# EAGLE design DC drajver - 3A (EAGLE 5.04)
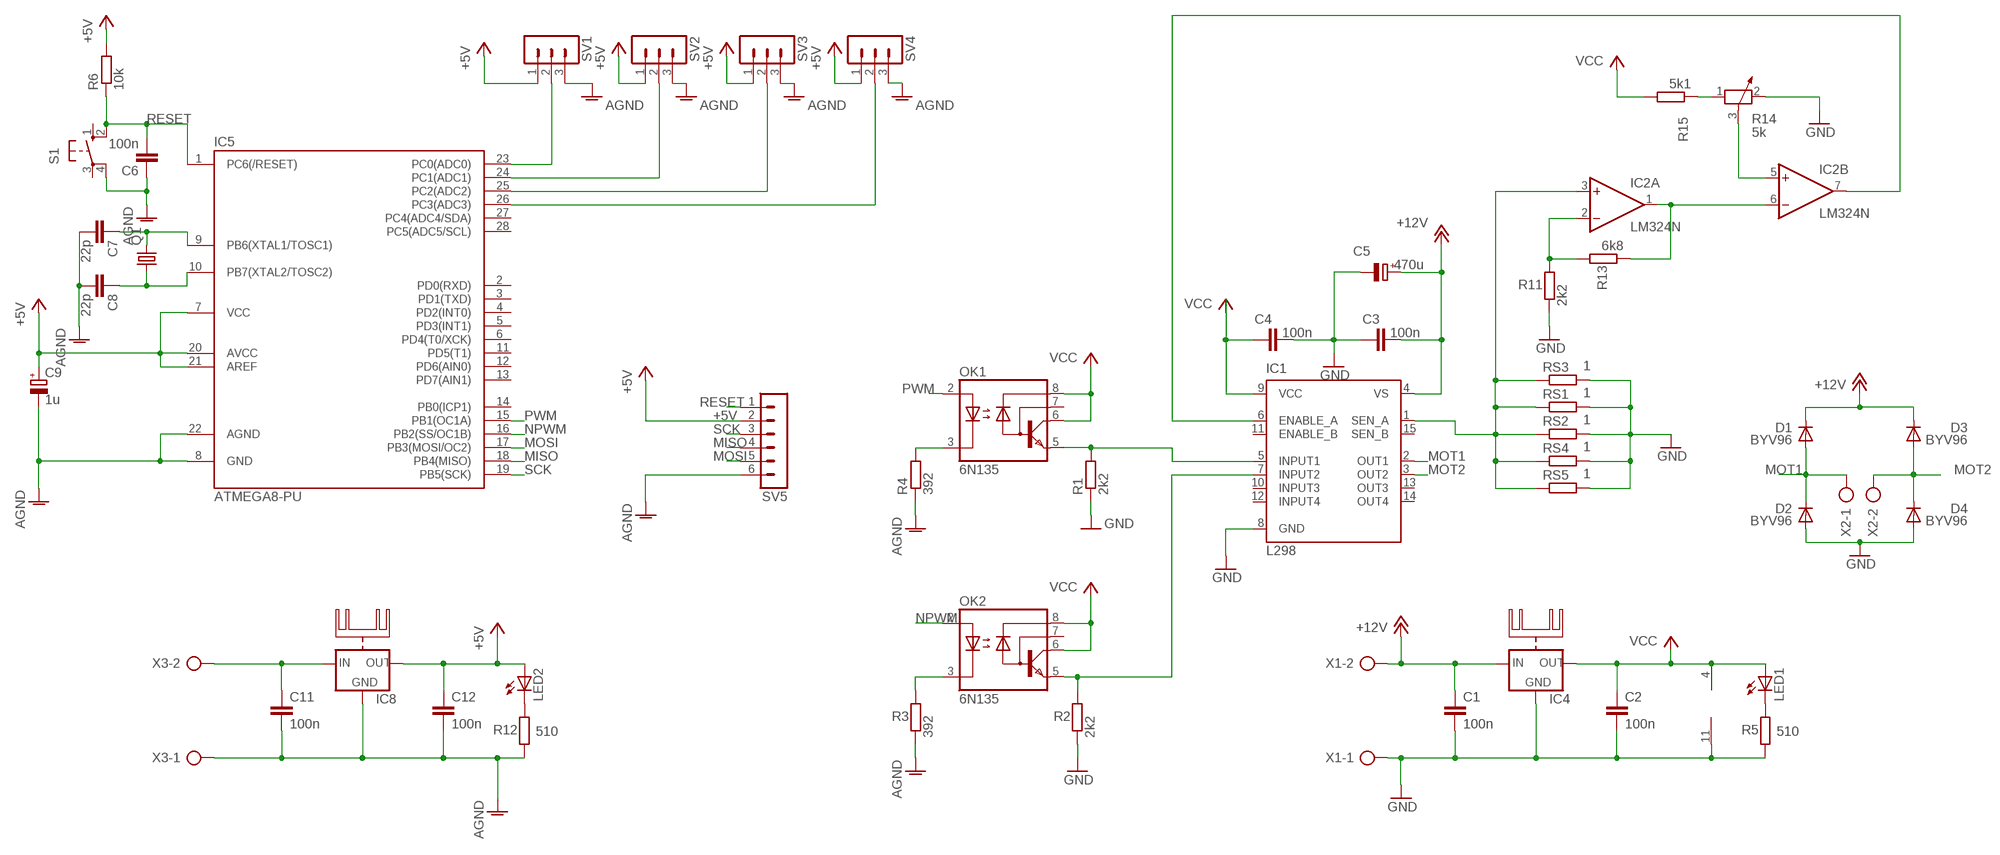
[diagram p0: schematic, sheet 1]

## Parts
C1  100n  C-EU050-024X044  [C050-024X044]
C2  100n  C-EU050-024X044  [C050-024X044]
C3  100n  C-EU050-024X044  [C050-024X044]
C4  100n  C-EU050-024X044  [C050-024X044]
C5  470u  CPOL-EUE3.5-8  [E3,5-8]
C6  100n  C-EU050-024X044  [C050-024X044]
C7  22p  C-EU050-024X044  [C050-024X044]
C8  22p  C-EU050-024X044  [C050-024X044]
C9  1u  CPOL-EUE2-4  [E2-4]
C11  100n  C-EU050-024X044  [C050-024X044]
C12  100n  C-EU050-024X044  [C050-024X044]
D1  BYV96  [SOD57-10]
D2  BYV96  [SOD57-10]
D3  BYV96  [SOD57-10]
D4  BYV96  [SOD57-10]
IC1  L298  [MULTIWATT-15]
IC2  LM324N  [DIL14]
IC4  78XXH  [78XXH]
IC5  ATMEGA8-PU  [DIL28-3]
IC8  78XXH  [78XXH]
LED1  LED3MM  [LED3MM]
LED2  LED3MM  [LED3MM]
OK1  6N135  [DIL08]
OK2  6N135  [DIL08]
Q1  CRYSTALHC49S  [HC49/S]
R1  2k2  R-EU_0207/7  [0207/7]
R2  2k2  R-EU_0207/7  [0207/7]
R3  392  R-EU_0207/7  [0207/7]
R4  392  R-EU_0207/7  [0207/7]
R5  510  R-EU_0207/7  [0207/7]
R6  10k  R-EU_0207/7  [0207/7]
R11  2k2  R-EU_0207/7  [0207/7]
R12  510  R-EU_0207/7  [0207/7]
R13  6k8  R-EU_0207/7  [0207/7]
R14  5k  POTENTIOMETER_PT-10  [PT-10]
R15  5k1  R-EU_0207/7  [0207/7]
RS1  1  R-EU_0617/5V  [0617V]
RS2  1  R-EU_0617/5V  [0617V]
RS3  1  R-EU_0617/5V  [0617V]
RS4  1  R-EU_0617/5V  [0617V]
RS5  1  R-EU_0617/5V  [0617V]
S1  10-XX  [B3F-10XX]
SV1  MA03-1  [MA03-1]
SV2  MA03-1  [MA03-1]
SV3  MA03-1  [MA03-1]
SV4  MA03-1  [MA03-1]
SV5  MA06-1  [MA06-1]
X1  AK500/2  [AK500/2]
X2  AK500/2  [AK500/2]
X3  AK500/2  [AK500/2]

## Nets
+5V: C9.+ C12.1 IC5.7(VCC) IC5.20(AVCC) IC5.21(AREF) IC8.OUT LED2.A R6.2 SV1.1 SV2.1 SV3.1 SV4.1 SV5.2
+12V: C1.1 C3.2 C5.+ D1.C D3.C IC1.4(VS) IC4.IN X1.2
AGND: C6.1 C7.2 C8.2 C9.- C11.2 C12.2 IC5.8(GND) IC5.22(AGND) IC8.GND R3.1 R4.1 R12.1 S1.4(P1) SV1.3 SV2.3 SV3.3 SV4.3 SV5.6 X3.1
GND: C1.2 C2.2 C3.1 C4.2 C5.- D2.A D4.A IC1.8(GND) IC2.11(P:V-) IC4.GND R1.1 R2.1 R5.1 R11.1 R14.2 RS1.2 RS2.2 RS3.2 RS4.2 RS5.2 X1.1
MISO: IC5.18(PB4(MISO)) SV5.4
MOSI: IC5.17(PB3(MOSI/OC2)) SV5.5
MOT1: D1.A D2.C IC1.2(OUT1) X2.1
MOT2: D3.A D4.C IC1.3(OUT2) X2.2
N$1: IC2.2(A:-IN) R11.2 R13.2
N$2: IC2.1(A:OUT) IC2.6(B:-IN) R13.1
N$3: LED1.K(C) R5.2
N$4: R14.1 R15.1
N$5: IC5.23(PC0(ADC0)) SV1.2
N$6: IC1.7(INPUT2) OK2.5(GND) R2.2
N$7: OK2.3(C) R3.2
N$8: OK1.3(C) R4.2
N$9: IC1.5(INPUT1) OK1.5(GND) R1.2
N$10: IC2.5(B:+IN) R14.3
N$12: IC5.24(PC1(ADC1)) SV2.2
N$13: C7.1 IC5.9(PB6(XTAL1/TOSC1)) Q1.2
N$14: C8.1 IC5.10(PB7(XTAL2/TOSC2)) Q1.1
N$15: IC1.1(SEN_A) IC2.3(A:+IN) RS1.1 RS2.1 RS3.1 RS4.1 RS5.1
N$16: IC5.25(PC2(ADC2)) SV3.2
N$17: IC5.26(PC3(ADC3)) SV4.2
N$22: C11.1 IC8.IN X3.2
N$23: LED2.K(C) R12.2
N$26: IC1.6(ENABLE_A) IC2.7(B:OUT)
NPWM: IC5.16(PB2(SS/OC1B)) OK2.2(A)
PWM: IC5.15(PB1(OC1A)) OK1.2(A)
RESET: C6.2 IC5.1(PC6(/RESET)) R6.1 S1.2(S1) SV5.1
SCK: IC5.19(PB5(SCK)) SV5.3
VCC: C2.1 C4.1 IC1.9(VCC) IC2.4(P:V+) IC4.OUT LED1.A OK1.6(VO) OK1.8(VCC) OK2.6(VO) OK2.8(VCC) R15.2
Unconnected: IC1.10(INPUT3) IC1.11(ENABLE_B) IC1.12(INPUT4) IC1.13(OUT3) IC1.14(OUT4) IC1.15(SEN_B) IC2.8(C:OUT) IC2.9(C:-IN) IC2.10(C:+IN) IC2.12(D:+IN) IC2.13(D:-IN) IC2.14(D:OUT) IC5.2(PD0(RXD)) IC5.3(PD1(TXD)) IC5.4(PD2(INT0)) IC5.5(PD3(INT1)) IC5.6(PD4(T0/XCK)) IC5.11(PD5(T1)) IC5.12(PD6(AIN0)) IC5.13(PD7(AIN1)) IC5.14(PB0(ICP1)) IC5.27(PC4(ADC4/SDA)) IC5.28(PC5(ADC5/SCL)) OK1.7(VB) OK2.7(VB) S1.1(S) S1.3(P)

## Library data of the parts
C1-C4 C6-C8 C11 C12 = rcl:C-EU: CAPACITOR, European symbol
C5 C9 = rcl:CPOL-EU: POLARIZED CAPACITOR, European symbol
D1-D4 = diode:BYV96: DIODE
IC1 = st-microelectronics:L298: DUAL FULL-BRIDGE DRIVER
IC2 = linear:LM324: OP AMP
IC4 IC8 = 78xx_with_heatsink:78XXH: VOLTAGE REGULATOR
IC5 = atmega8:ATMEGA8-PU
LED1 LED2 = led:LED: LED
OK1 OK2 = optocoupler:6N135: MOTOROLA OPTO COUPLER
Q1 = crystal:CRYSTAL: CRYSTAL
R1-R6 R11-R13 R15 RS1-RS5 = rcl:R-EU_: RESISTOR, European symbol
R14 = rcl:POTENTIOMETER_: Potentiometer
S1 = switch-omron:10-XX: OMRON SWITCH
SV1-SV4 = con-lstb:MA03-1: PIN HEADER
SV5 = con-lstb:MA06-1: PIN HEADER
X1-X3 = con-ptr500:AK500/2: CONNECTOR

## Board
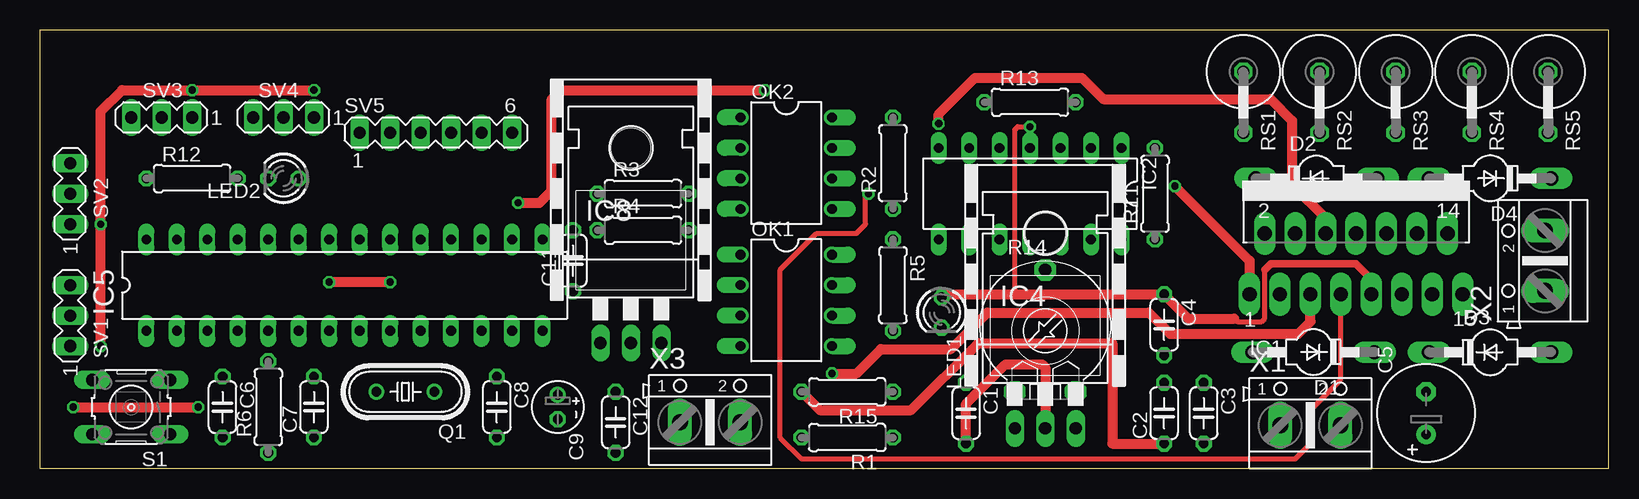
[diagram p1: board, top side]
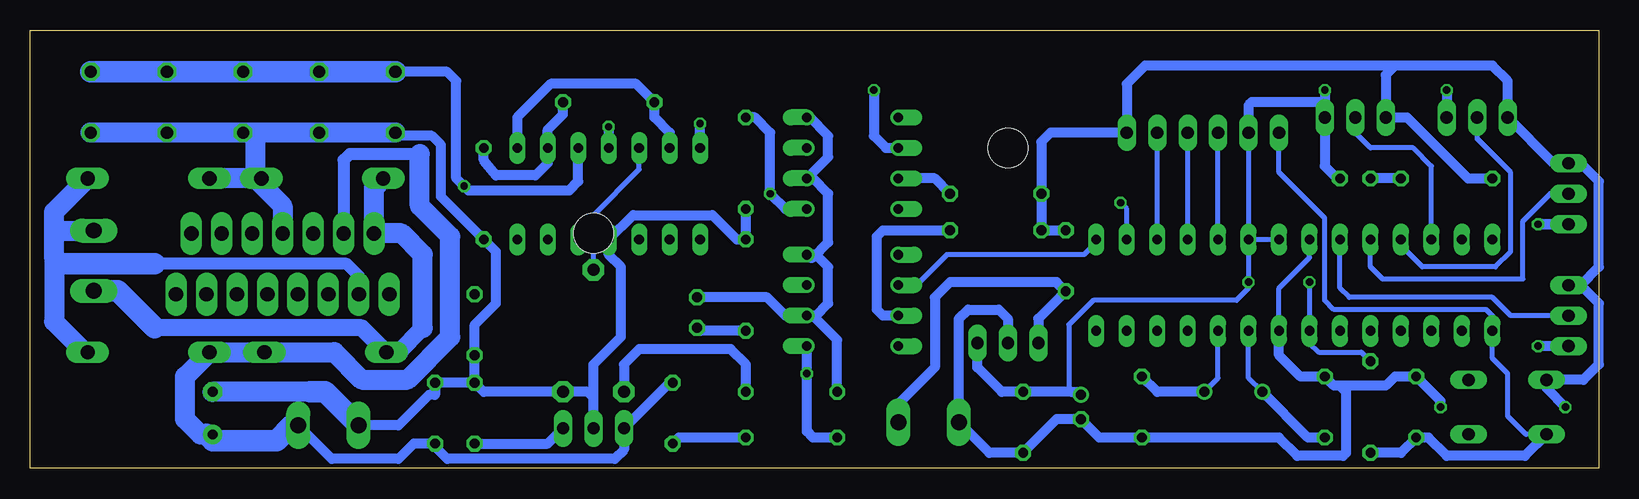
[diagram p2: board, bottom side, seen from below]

Size 130.79 x 36.5 mm. Coordinates in mm from the lower left corner, seen from the top.
Outline: 0,0 130.79,0 130.79,36.5 0,36.5 0,0
Copper layers (1*16): Top 0.035mm / dielectric 1.5mm / Bottom 0.035mm
Design rules "default": minimum track width 10mil, minimum drill 24mil, track to track 8mil, track to pad 8mil, pad to pad 8mil, via to via 8mil, smd to smd 8mil, copper to edge 40mil, drill to drill 8mil, minimum pad ring 10mil, minimum via ring 8mil, stop-mask expansion 4mil, vias tented up to drill 0mil, thermal gap 10mil

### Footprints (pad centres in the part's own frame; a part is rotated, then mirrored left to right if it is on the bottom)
C050-024X044 = drill 0.813 octagon: 1 -2.54,0; 2 2.54,0
E3,5-8 = drill 0.813 pad 1.6 round: + -1.778,0 | drill 0.813 pad 1.6 octagon: - 1.778,0
E2-4 = drill 0.813 pad 1.27 round: + -1.016,0 | drill 0.813 pad 1.27 octagon: - 1.016,0
SOD57-10 = drill 1.194 long: A 5.08,0; C -5.08,0
MULTIWATT-15 = drill 1.2 long: 1 -8.89,-7.62; 2 -7.62,-2.54; 3 -6.35,-7.62; 4 -5.08,-2.54; 5 -3.81,-7.62; 6 -2.54,-2.54; 7 -1.27,-7.62; 8 0,-2.54; 9 1.27,-7.62; 10 2.54,-2.54; 11 3.81,-7.62; 12 5.08,-2.54; 13 6.35,-7.62; 14 7.62,-2.54; 15 8.89,-7.62
DIL14 = drill 0.813 long: 1 -7.62,-3.81; 2 -5.08,-3.81; 3 -2.54,-3.81; 4 0,-3.81; 5 2.54,-3.81; 6 5.08,-3.81; 7 7.62,-3.81; 8 7.62,3.81; 9 5.08,3.81; 10 2.54,3.81; 11 0,3.81; 12 -2.54,3.81; 13 -5.08,3.81; 14 -7.62,3.81
78XXH = drill 1.016 long: GND 0,-5.08; IN -2.54,-5.08; OUT 2.54,-5.08 | hole 3.302: 0,11.176
DIL28-3 = drill 0.813 long: 1 -16.51,-3.81; 2 -13.97,-3.81; 3 -11.43,-3.81; 4 -8.89,-3.81; 5 -6.35,-3.81; 6 -3.81,-3.81; 7 -1.27,-3.81; 8 1.27,-3.81; 9 3.81,-3.81; 10 6.35,-3.81; 11 8.89,-3.81; 12 11.43,-3.81; 13 13.97,-3.81; 14 16.51,-3.81; 15 16.51,3.81; 16 13.97,3.81; 17 11.43,3.81; 18 8.89,3.81; 19 6.35,3.81; 20 3.81,3.81; 21 1.27,3.81; 22 -1.27,3.81; 23 -3.81,3.81; 24 -6.35,3.81; 25 -8.89,3.81; 26 -11.43,3.81; 27 -13.97,3.81; 28 -16.51,3.81
LED3MM = drill 0.813 octagon: A -1.27,0; K 1.27,0
DIL08 = drill 0.813 offset: 1 -3.81,-3.81; 2 -1.27,-3.81; 3 1.27,-3.81; 4 3.81,-3.81; 5 3.81,3.81; 6 1.27,3.81; 7 -1.27,3.81; 8 -3.81,3.81
HC49/S = drill 0.813 round: 1 -2.413,0; 2 2.413,0
0207/7 = drill 0.813 octagon: 1 -3.81,0; 2 3.81,0
PT-10 = drill 1.016 pad 1.778 octagon: 1 -2.54,-5.08; 2 2.54,-5.08; 3 0,5.08
0617V = drill 1.016 octagon: 1 -2.54,0; 2 2.54,0
B3F-10XX = drill 1.016 long: 1 -3.251,2.261; 2 3.251,2.261; 3 -3.251,-2.261; 4 3.251,-2.261
MA03-1 = drill 1.016 long: 1 -2.54,0; 2 0,0; 3 2.54,0
MA06-1 = drill 1.016 long: 1 -6.35,0; 2 -3.81,0; 3 -1.27,0; 4 1.27,0; 5 3.81,0; 6 6.35,0
AK500/2 = drill 1.321 long: 1 -2.515,0; 2 2.515,0

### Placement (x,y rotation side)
C1  77.22,4.57 270 top
C2  93.73,4.57 90 top
C3  97.03,4.57 270 top
C4  93.73,11.94 270 top
C5  115.57,4.57 90 top
C6  15.24,5.08 270 top
C7  22.86,5.08 90 top
C8  38.1,5.08 270 top
C9  43.18,5.08 270 top
C11  44.45,17.27 90 top
C12  48.01,3.81 270 top
D1  106.17,9.65 180 top
D2  106.43,24.13 0 top
D3  120.9,9.65 0 top
D4  120.9,24.13 180 top
IC1  109.73,22.1 0 top
IC2  82.55,22.86 180 top
IC4  83.82,8.38 0 top
IC5  25.4,15.24 0 top
IC8  49.28,15.49 0 top
LED1  75.18,12.95 270 top
LED2  20.32,24.13 180 top
OK1  62.23,13.97 270 top
OK2  62.23,25.4 270 top
Q1  30.48,6.35 180 top
R1  67.31,2.54 180 top
R2  71.12,25.4 90 top
R3  50.29,22.86 0 top
R4  50.29,19.81 0 top
R5  71.12,15.24 270 top
R6  19.05,5.08 90 top
R11  92.96,22.86 90 top
R12  12.7,24.13 0 top
R13  82.55,30.48 0 top
R14  83.82,11.43 0 top
R15  67.31,6.35 180 top
RS1  100.33,30.48 270 top
RS2  106.68,30.48 270 top
RS3  113.03,30.48 270 top
RS4  119.38,30.48 270 top
RS5  125.73,30.48 270 top
S1  7.62,5.08 180 top
SV1  2.54,12.7 90 top
SV2  2.54,22.86 90 top
SV3  10.16,29.21 180 top
SV4  20.32,29.21 180 top
SV5  33.02,27.94 0 top
X1  105.92,3.56 0 top
X2  125.48,17.27 90 top
X3  55.88,3.81 0 top

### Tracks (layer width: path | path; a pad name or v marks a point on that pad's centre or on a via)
+5V  (via drill 0.6)
  Top 0.813: v5.08,10.16 5.08,20.07 | 5.08,20.07 v5.08,20.32 | 5.08,20.07 5.08,29.72 6.86,31.5 v12.7,31.5 v22.86,31.5 | v29.21,15.49 v24.13,15.49
  Bottom 0.406: R6.2 19.81,9.65 23.37,9.65 24.13,10.41 IC5.7 v24.13,15.49 | IC5.20 IC5.21 | SV5.2 IC5.20 | IC5.20 v29.21,15.49 | v29.21,15.49 29.21,14.99 30.23,13.97 42.16,13.97 44.2,11.94 44.2,6.6 43.94,6.35 | IC5.20 v29.21,15.49
  Bottom 0.813: LED2.A 21.84,24.13 22.86,25.15 SV4.1 22.86,30.48 | SV1.1 v5.08,10.16 | v22.86,31.5 22.86,30.48 | SV5.2 29.21,30.23 28.96,30.48 22.86,30.48 | IC8.OUT 51.82,8.38 49.78,6.35 C12.1 43.94,6.35 43.43,6.35 C9.+ | v5.08,20.32 SV2.1 v5.08,20.32 | v12.7,31.5 SV3.1 v12.7,31.5
+12V
  Bottom 0.813: X1.2 105.64,0.76 100.08,0.76 98.81,2.03 C3.2 97.03,1.78 96.01,0.76 82.04,0.76 81.28,1.52 IC4.IN 77.47,7.11 C1.1
  Bottom 1.016: 98.3,26.16 104.14,26.16 104.65,25.65 IC1.4
  Bottom 1.676: C5.+ 116.08,2.79 116.59,2.79 117.86,4.06 117.86,7.62 D3.C D1.C 105.41,9.65 103.12,7.37 99.31,7.37 95.76,10.92 95.76,19.3 98.3,21.84 98.3,26.16
  Bottom 1.778: X1.2 108.97,3.56 110.24,2.29 115.57,2.29 116.08,2.79
AGND  (via drill 0.6)
  Top 0.813: v2.79,5.08 v13.21,5.08
  Bottom 0.406: IC5.22 24.13,17.53 26.67,14.99 IC5.8
  Bottom 0.813: 1.52,15.24 0,13.72 0,8.64 1.29,7.34 S1.4 4.37,6.65 v2.79,5.08 | 1.52,15.24 SV1.3 | 1.52,15.24 0,16.76 0,23.88 1.52,25.4 SV2.3 3.81,25.4 SV3.3 7.62,32.26 8.89,33.53 16.26,33.53 | R12.1 10.92,24.13 16,29.21 SV4.3 17.78,32.77 17.02,33.53 16.26,33.53 | 21.59,6.86 17.78,6.86 17.02,7.62 C6.1 13.21,5.59 v13.21,5.08 | 21.59,6.86 22.1,6.86 C7.2 24.89,7.62 26.67,9.4 IC5.8 | 21.59,6.86 21.08,6.35 21.08,1.27 21.34,1.02 25.15,1.02 26.67,2.54 C8.2 41.66,2.54 C9.- 45.21,4.06 C12.2 50.83,1.27 X3.1 53.37,12.42 52.58,13.21 50.04,13.21 49.28,12.45 IC8.GND | R4.1 C11.2 | R4.1 R3.1 46.48,27.18 | 46.48,27.18 R4.1 | 46.48,27.18 45.72,27.94 SV5.6 39.37,32 37.85,33.53 16.26,33.53
GND
  Top 0.813: C1.2 77.22,5.33 80.52,8.64 83.57,8.64 83.82,8.38 IC4.GND
  Bottom 0.813: R1.1 76.71,2.54 C1.2 | R2.1 R5.1 71.88,19.05 73.91,21.08 80.52,21.08 IC2.11 82.55,17.78 81.53,16.76 81.53,10.92 83.82,8.64 83.82,5.33 | RS1.2 100.08,27.69 97.28,27.69 96.52,26.92 96.52,22.61 R11.1 91.95,18.03 91.95,13.72 93.73,11.94 C4.2 C2.2 | X1.1 100.08,3.56 97.54,6.1 97.03,6.1 C3.1 C2.2 | IC4.GND 83.82,5.33 | 83.82,5.33 83.82,5.84 84.33,6.35 R14.2 92.96,6.35 C2.2
  Bottom 1.676: RS5.2 RS4.2 RS3.2 112.01,27.94 | 112.01,27.94 RS2.2 RS1.2 | 112.01,24.13 D2.A | 112.01,24.13 D4.A | IC1.8 109.73,21.84 112.01,24.13 | 112.01,27.94 112.01,24.13 | 106.96,6.35 107.44,6.35 C5.-
  Bottom 1.778: X1.1 103.4,3.58 106.17,6.35 107.44,6.35
MISO
  Bottom 0.406: IC5.18 SV5.4
MOSI
  Bottom 0.406: IC5.17 SV5.5
MOT1
  Bottom 1.422: 100.08,9.65 98.04,11.68 | 120.4,11.68 103.12,11.68 D1.A
  Bottom 1.676: D2.C 102.11,23.37 IC1.2 99.82,19.56 98.04,17.78 98.04,11.68 | D1.A 100.08,9.65
  Bottom 1.778: X2.1 123.47,14.76 120.4,11.68
MOT2
  Bottom 1.016: IC1.3 103.38,16 104.39,17.02 120.4,17.02
  Bottom 1.676: D3.A 126.24,9.65 128.78,12.19 128.78,17.53 | X2.2 128.5,19.79 128.52,19.81 128.78,19.81 | 128.78,17.53 128.78,19.81 | 128.78,19.81 128.78,21.34 D4.C | 128.27,17.02 128.78,17.53
  Bottom 1.778: 120.4,17.02 128.27,17.02 128.52,16.76
N$1
  Bottom 0.813: R13.2 86.36,29.46 87.63,28.19 IC2.2 87.63,25.4 88.65,24.38 91.95,24.38 92.96,25.65 R11.2
N$2
  Bottom 0.813: IC2.6 77.47,27.94 78.74,29.21 R13.1 80.26,32 87.38,32 90.17,29.21 IC2.1
N$3
  Bottom 0.813: R5.2 74.93,11.43 LED1.K
N$4
  Bottom 0.813: R15.1 71.12,8.64 72.39,9.91 80.01,9.91 81.28,8.64 R14.1
N$5
  Bottom 0.406: IC5.23 21.59,14.99 20.83,14.22 8.89,14.22 7.37,12.7 SV1.2
N$6  (via drill 0.6)
  Top 0.406: v69.09,22.86 68.83,22.61 68.83,20.32 68.07,19.56 64.77,19.56 61.72,16.51 61.72,2.54 63.5,0.76 104.65,0.76 105.92,2.03 105.92,4.83 108.46,7.37 IC1.7
  Bottom 0.813: OK2.5 67.82,21.59 v69.09,22.86 69.09,27.94 70.36,29.21 R2.2
N$7
  Bottom 0.813: R3.2 55.37,24.13 OK2.3
N$8
  Bottom 0.813: R4.2 59.69,19.81 60.2,19.3 60.2,13.21 59.69,12.7 OK1.3
N$9  (via drill 0.6)
  Top 0.813: IC1.5 105.92,12.19 104.9,11.18 94.23,11.18 92.46,12.95 78.99,12.95 75.95,9.91 70.1,9.91 68.07,7.87 v66.04,7.87
  Bottom 0.813: R1.2 65.53,2.54 66.04,3.05 v66.04,7.87 OK1.5
N$10
  Bottom 0.406: IC2.5 80.01,24.89 83.82,21.08 R14.3
N$12
  Bottom 0.406: IC5.24 19.05,16.76 18.03,15.75 6.35,15.75 6.35,20.57 4.06,22.86 SV2.2
N$13
  Bottom 0.406: IC5.9 29.21,7.49 Q1.2
  Bottom 0.813: C7.1 24.26,2.54 Q1.2
N$14
  Bottom 0.406: IC5.10 31.75,7.49 Q1.1
  Bottom 0.813: Q1.1 36.83,6.35 C8.1
N$15  (via drill 0.6)
  Top 0.813: IC1.1 100.84,17.27 v94.61,23.49
  Bottom 0.813: RS1.1 96.01,33.02 95.25,32.26 95.25,24.13 v94.61,23.49 94.49,23.37 94.23,23.11 85.85,23.11 85.09,23.88 IC2.3
  Bottom 1.778: RS2.1 RS3.1 | RS3.1 RS4.1 | RS4.1 RS5.1 RS4.1 | RS2.1 RS3.1 | RS3.1 RS4.1 | RS3.1 RS4.1 | RS1.1 RS2.1
N$16
  Bottom 0.406: IC5.25 16.51,18.54 14.73,16.76 8.64,16.76 7.37,18.03 7.37,24.64 10.16,27.43 SV3.2
N$17
  Bottom 0.406: IC5.26 13.97,25.15 15.49,26.67 19.05,26.67 20.32,27.94 SV4.2
N$22
  Bottom 0.813: IC8.IN 46.74,12.45 C11.1 45.21,15.49 54.1,15.49 55.37,14.22 55.37,8.38 58.4,5.36 X3.2
N$23
  Bottom 0.813: R12.2 LED2.K
N$26  (via drill 0.6)
  Top 0.813: IC1.6 107.19,20.83 104.39,23.62 104.39,28.96 102.62,30.73 88.65,30.73 86.87,32.51 77.98,32.51 74.93,29.46 v74.93,28.7
  Bottom 0.813: IC2.7 v74.93,28.7
NPWM  (via drill 0.6)
  Top 0.813: v39.88,22.1 41.66,22.1 42.67,23.11 42.67,30.73 43.43,31.5 v60.45,31.5
  Bottom 0.406: IC5.16 39.37,21.59 v39.88,22.1
  Bottom 0.813: v60.45,31.5 60.45,27.69 59.44,26.67 OK2.2
PWM
  Bottom 0.406: IC5.15 41.91,18.8 42.93,17.78 54.36,17.78 56.9,15.24 OK1.2
RESET
  Bottom 0.406: S1.2 4.39,2.79 6.1,2.79 7.62,4.32 7.62,7.87 8.89,9.14 IC5.1 8.89,12.7 9.4,13.21 22.1,13.21 22.86,13.97 22.86,20.83 26.67,24.64 SV5.1
  Bottom 0.813: R6.1 16.51,1.27 C6.2 14.22,2.54 12.7,1.02 6.17,1.02 S1.2
SCK
  Bottom 0.406: IC5.19 SV5.3
VCC  (via drill 0.6)
  Top 0.406: v82.55,28.45 81.53,28.45 81.28,28.19 81.28,14.48 | 102.11,16.51 102.11,12.45 101.85,12.19 99.82,12.19 99.57,12.45
  Top 0.61: IC1.9 111,15.75 109.73,17.02 102.62,17.02 102.11,16.51
  Top 0.813: LED1.A 75.44,14.48 81.28,14.48 C4.1 95.76,12.45 99.57,12.45 | C2.1 89.41,2.03 89.41,10.41 78.23,10.41 72.64,4.83 65.02,4.83 R15.2
  Bottom 0.813: OK2.8 65.79,29.21 64.26,27.69 64.26,25.91 OK2.6 65.53,24.13 64.26,22.86 64.26,18.8 65.53,17.53 65.79,17.53 OK1.8 65.28,17.78 64.26,16.76 64.26,13.72 65.28,12.7 OK1.6 | OK1.6 65.53,12.7 63.5,10.67 R15.2 | OK1.6 67.82,12.7 69.34,14.22 LED1.A | C2.1 87.63,2.03 IC4.OUT | v82.55,28.45 IC2.4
